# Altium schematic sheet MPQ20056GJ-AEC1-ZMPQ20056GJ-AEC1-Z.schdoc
size 127 x 101 mm
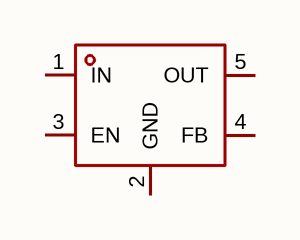
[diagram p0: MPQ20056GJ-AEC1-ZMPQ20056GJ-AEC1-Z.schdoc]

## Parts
U?  mpq20056gj-aec1-z  [TSOT-23-5_L2.9-W1.6-P0.95-LS2.8-BR]  (value not drawn)

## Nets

Not connected (* = marked no-connect by the designer): U? 1(IN) 2(GND) 3(EN) 4(FB) 5(OUT)

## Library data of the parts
U? = mpq20056gj-aec1-z: 输出极性:正极;工作电压:5.5V;输出电压:800mV~5V;输出电流:250mA;电源纹波抑制比(PSRR):63dB;输出类型:可调;; Manufacturer: MPS(芯源); AddInBom: yes; ModelId: b5108020abe84f7bb0f3c398b43b6e0b; ModelName: TSOT-23-5_L2.9-W1.6-H1.00-LS2.8-P0.95; ModelTransform: 110.45568,114.173,0,180,0,0,0,0,0; Output Configuration: 正极; Voltage - Supply: 5.5V; Output Current: 250mA; Power Supply Rejection Ratio (PSRR): 63dB; Voltage Dropout: 100mV@(250mA); standby current: 150uA; Noise: 13uVrms; Output Type: 可调; Number of Outputs: 1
